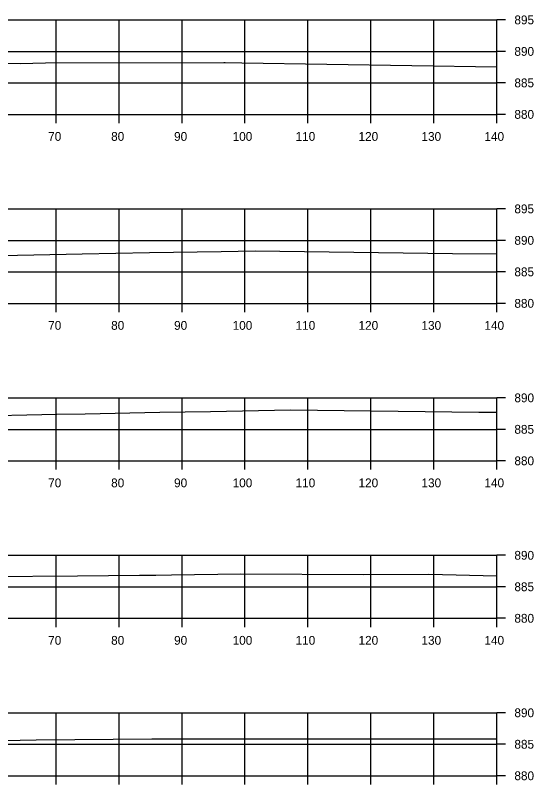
# Model space of a CAD drawing. Extents: x 1098669 to 1198896, y 698679 to 704410.
# Drawn here: x 1112059.1 to 1112141.4, y 701444.6 to 701566.7 of the extents above; entities that cross this region are included whole.
import ezdxf

# ---------------------------------------------------------------- set-up
doc = ezdxf.new("R2010")
doc.units = 0
for name, color, linetype in [('Proposed Surface', 7, 'Continuous'), ('R_Axis', 7, 'Continuous'), ('R_Axis Annot', 7, 'Continuous'), ('R_Grid', 7, 'Continuous')]:
    doc.layers.add(name, color=color, linetype=linetype)

msp = doc.modelspace()

# ---------------------------------------------------------------- linework, layer by layer
at = {"layer": 'Proposed Surface'}
for points in [[(1112045.42, 701559.17), (1112059.86, 701559.13), (1112063.84, 701559.21), (1112092.17, 701559.26), (1112092.43, 701559.26), (1112095.04, 701559.23), (1112135.55, 701558.57)], [(1112056.86, 701528.62), (1112069.69, 701528.88), (1112080.37, 701529.1), (1112091.79, 701529.28), (1112097.19, 701529.35), (1112128.54, 701528.96), (1112135.55, 701528.88)], [(1112051.27, 701503.14), (1112065.68, 701503.43), (1112070.17, 701503.5), (1112082.01, 701503.74), (1112090.08, 701503.87), (1112102.78, 701504.1), (1112132.72, 701503.76), (1112135.55, 701503.73)], [(1112054.65, 701477.68), (1112068.95, 701477.75), (1112078.81, 701477.86), (1112081.41, 701477.88), (1112083.9, 701477.93), (1112094.91, 701478.11), (1112114.31, 701477.97), (1112124.76, 701478.02), (1112135.55, 701477.79)], [(1112041.49, 701451.48), (1112059.82, 701451.68), (1112062.38, 701451.71), (1112080.76, 701451.91), (1112102.41, 701451.91), (1112104.3, 701451.9), (1112104.97, 701451.9), (1112126.57, 701451.91), (1112135.55, 701451.89)]]:
    msp.add_lwpolyline(points, dxfattribs=at)
at = {"layer": 'R_Axis'}
for p, q in [((1112135.55, 701551.03), (1112135.55, 701566.03)), ((1112136.95, 701566.03), (1112135.55, 701566.03)), ((1112136.95, 701561.03), (1112135.55, 701561.03)), ((1112136.95, 701556.03), (1112135.55, 701556.03)), ((1111855.55, 701551.03), (1112135.55, 701551.03)), ((1112065.55, 701549.63), (1112065.55, 701551.03)), ((1112075.55, 701549.63), (1112075.55, 701551.03)), ((1112085.55, 701549.63), (1112085.55, 701551.03)), ((1112095.55, 701549.63), (1112095.55, 701551.03)), ((1112105.55, 701549.63), (1112105.55, 701551.03)), ((1112115.55, 701549.63), (1112115.55, 701551.03)), ((1112125.55, 701549.63), (1112125.55, 701551.03)), ((1112135.55, 701549.63), (1112135.55, 701551.03)), ((1112136.95, 701551.03), (1112135.55, 701551.03)), ((1112135.55, 701521.03), (1112135.55, 701536.03)), ((1112136.95, 701536.03), (1112135.55, 701536.03)), ((1112136.95, 701531.03), (1112135.55, 701531.03)), ((1112136.95, 701526.03), (1112135.55, 701526.03)), ((1111855.55, 701521.03), (1112135.55, 701521.03)), ((1112065.55, 701519.63), (1112065.55, 701521.03)), ((1112075.55, 701519.63), (1112075.55, 701521.03)), ((1112085.55, 701519.63), (1112085.55, 701521.03)), ((1112095.55, 701519.63), (1112095.55, 701521.03)), ((1112105.55, 701519.63), (1112105.55, 701521.03)), ((1112115.55, 701519.63), (1112115.55, 701521.03)), ((1112125.55, 701519.63), (1112125.55, 701521.03)), ((1112135.55, 701519.63), (1112135.55, 701521.03)), ((1112136.95, 701521.03), (1112135.55, 701521.03)), ((1112135.55, 701496.03), (1112135.55, 701506.03)), ((1112136.95, 701506.03), (1112135.55, 701506.03)), ((1112136.95, 701501.03), (1112135.55, 701501.03)), ((1111855.55, 701496.03), (1112135.55, 701496.03)), ((1112065.55, 701494.63), (1112065.55, 701496.03)), ((1112075.55, 701494.63), (1112075.55, 701496.03)), ((1112085.55, 701494.63), (1112085.55, 701496.03)), ((1112095.55, 701494.63), (1112095.55, 701496.03)), ((1112105.55, 701494.63), (1112105.55, 701496.03)), ((1112115.55, 701494.63), (1112115.55, 701496.03)), ((1112125.55, 701494.63), (1112125.55, 701496.03)), ((1112135.55, 701494.63), (1112135.55, 701496.03)), ((1112136.95, 701496.03), (1112135.55, 701496.03)), ((1112135.55, 701471.03), (1112135.55, 701481.03)), ((1112136.95, 701481.03), (1112135.55, 701481.03)), ((1112136.95, 701476.03), (1112135.55, 701476.03)), ((1111855.55, 701471.03), (1112135.55, 701471.03)), ((1112065.55, 701469.63), (1112065.55, 701471.03)), ((1112075.55, 701469.63), (1112075.55, 701471.03)), ((1112085.55, 701469.63), (1112085.55, 701471.03)), ((1112095.55, 701469.63), (1112095.55, 701471.03)), ((1112105.55, 701469.63), (1112105.55, 701471.03)), ((1112115.55, 701469.63), (1112115.55, 701471.03)), ((1112125.55, 701469.63), (1112125.55, 701471.03)), ((1112135.55, 701469.63), (1112135.55, 701471.03)), ((1112136.95, 701471.03), (1112135.55, 701471.03)), ((1112135.55, 701446.03), (1112135.55, 701456.03)), ((1112136.95, 701456.03), (1112135.55, 701456.03)), ((1112136.95, 701451.03), (1112135.55, 701451.03)), ((1111855.55, 701446.03), (1112135.55, 701446.03)), ((1112065.55, 701444.63), (1112065.55, 701446.03)), ((1112075.55, 701444.63), (1112075.55, 701446.03)), ((1112085.55, 701444.63), (1112085.55, 701446.03)), ((1112095.55, 701444.63), (1112095.55, 701446.03)), ((1112105.55, 701444.63), (1112105.55, 701446.03)), ((1112115.55, 701444.63), (1112115.55, 701446.03)), ((1112125.55, 701444.63), (1112125.55, 701446.03)), ((1112135.55, 701444.63), (1112135.55, 701446.03)), ((1112136.95, 701446.03), (1112135.55, 701446.03))]:
    msp.add_line(p, q, dxfattribs=at)
at = {"layer": 'R_Grid'}
for p, q in [((1111855.55, 701566.03), (1112135.55, 701566.03)), ((1112065.55, 701551.03), (1112065.55, 701566.03)), ((1112075.55, 701551.03), (1112075.55, 701566.03)), ((1112085.55, 701551.03), (1112085.55, 701566.03)), ((1112095.55, 701551.03), (1112095.55, 701566.03)), ((1112105.55, 701551.03), (1112105.55, 701566.03)), ((1112115.55, 701551.03), (1112115.55, 701566.03)), ((1112125.55, 701551.03), (1112125.55, 701566.03)), ((1112135.55, 701551.03), (1112135.55, 701566.03)), ((1111855.55, 701561.03), (1112135.55, 701561.03)), ((1111855.55, 701556.03), (1112135.55, 701556.03)), ((1111855.55, 701551.03), (1112135.55, 701551.03)), ((1111855.55, 701536.03), (1112135.55, 701536.03)), ((1112065.55, 701521.03), (1112065.55, 701536.03)), ((1112075.55, 701521.03), (1112075.55, 701536.03)), ((1112085.55, 701521.03), (1112085.55, 701536.03)), ((1112095.55, 701521.03), (1112095.55, 701536.03)), ((1112105.55, 701521.03), (1112105.55, 701536.03)), ((1112115.55, 701521.03), (1112115.55, 701536.03)), ((1112125.55, 701521.03), (1112125.55, 701536.03)), ((1112135.55, 701521.03), (1112135.55, 701536.03)), ((1111855.55, 701531.03), (1112135.55, 701531.03)), ((1111855.55, 701526.03), (1112135.55, 701526.03)), ((1111855.55, 701521.03), (1112135.55, 701521.03)), ((1111855.55, 701506.03), (1112135.55, 701506.03)), ((1112065.55, 701496.03), (1112065.55, 701506.03)), ((1112075.55, 701496.03), (1112075.55, 701506.03)), ((1112085.55, 701496.03), (1112085.55, 701506.03)), ((1112095.55, 701496.03), (1112095.55, 701506.03)), ((1112105.55, 701496.03), (1112105.55, 701506.03)), ((1112115.55, 701496.03), (1112115.55, 701506.03)), ((1112125.55, 701496.03), (1112125.55, 701506.03)), ((1112135.55, 701496.03), (1112135.55, 701506.03)), ((1111855.55, 701501.03), (1112135.55, 701501.03)), ((1111855.55, 701496.03), (1112135.55, 701496.03)), ((1111855.55, 701481.03), (1112135.55, 701481.03)), ((1112065.55, 701471.03), (1112065.55, 701481.03)), ((1112075.55, 701471.03), (1112075.55, 701481.03)), ((1112085.55, 701471.03), (1112085.55, 701481.03)), ((1112095.55, 701471.03), (1112095.55, 701481.03)), ((1112105.55, 701471.03), (1112105.55, 701481.03)), ((1112115.55, 701471.03), (1112115.55, 701481.03)), ((1112125.55, 701471.03), (1112125.55, 701481.03)), ((1112135.55, 701471.03), (1112135.55, 701481.03)), ((1111855.55, 701476.03), (1112135.55, 701476.03)), ((1111855.55, 701471.03), (1112135.55, 701471.03)), ((1111855.55, 701456.03), (1112135.55, 701456.03)), ((1112065.55, 701446.03), (1112065.55, 701456.03)), ((1112075.55, 701446.03), (1112075.55, 701456.03)), ((1112085.55, 701446.03), (1112085.55, 701456.03)), ((1112095.55, 701446.03), (1112095.55, 701456.03)), ((1112105.55, 701446.03), (1112105.55, 701456.03)), ((1112115.55, 701446.03), (1112115.55, 701456.03)), ((1112125.55, 701446.03), (1112125.55, 701456.03)), ((1112135.55, 701446.03), (1112135.55, 701456.03)), ((1111855.55, 701451.03), (1112135.55, 701451.03)), ((1111855.55, 701446.03), (1112135.55, 701446.03))]:
    msp.add_line(p, q, dxfattribs=at)

# ---------------------------------------------------------------- texts
at = {"layer": 'R_Axis Annot'}
for s, p in [('895', (1112138.35, 701565.33)), ('890', (1112138.35, 701560.33)), ('885', (1112138.35, 701555.33)), ('880', (1112138.35, 701550.33)), ('70', (1112064.29, 701546.83)), ('80', (1112074.29, 701546.83)), ('90', (1112084.29, 701546.83)), ('100', (1112093.59, 701546.83)), ('110', (1112103.59, 701546.83)), ('120', (1112113.59, 701546.83)), ('130', (1112123.59, 701546.83)), ('140', (1112133.59, 701546.83)), ('895', (1112138.35, 701535.33)), ('890', (1112138.35, 701530.33)), ('885', (1112138.35, 701525.33)), ('880', (1112138.35, 701520.33)), ('70', (1112064.29, 701516.83)), ('80', (1112074.29, 701516.83)), ('90', (1112084.29, 701516.83)), ('100', (1112093.59, 701516.83)), ('110', (1112103.59, 701516.83)), ('120', (1112113.59, 701516.83)), ('130', (1112123.59, 701516.83)), ('140', (1112133.59, 701516.83)), ('890', (1112138.35, 701505.33)), ('885', (1112138.35, 701500.33)), ('880', (1112138.35, 701495.33)), ('70', (1112064.29, 701491.83)), ('80', (1112074.29, 701491.83)), ('90', (1112084.29, 701491.83)), ('100', (1112093.59, 701491.83)), ('110', (1112103.59, 701491.83)), ('120', (1112113.59, 701491.83)), ('130', (1112123.59, 701491.83)), ('140', (1112133.59, 701491.83)), ('890', (1112138.35, 701480.33)), ('885', (1112138.35, 701475.33)), ('880', (1112138.35, 701470.33)), ('70', (1112064.29, 701466.83)), ('80', (1112074.29, 701466.83)), ('90', (1112084.29, 701466.83)), ('100', (1112093.59, 701466.83)), ('110', (1112103.59, 701466.83)), ('120', (1112113.59, 701466.83)), ('130', (1112123.59, 701466.83)), ('140', (1112133.59, 701466.83)), ('890', (1112138.35, 701455.33)), ('885', (1112138.35, 701450.33)), ('880', (1112138.35, 701445.33))]:
    msp.add_text(s, height=1.4, dxfattribs=at).set_placement(p)

doc.saveas('drawing.dxf')
